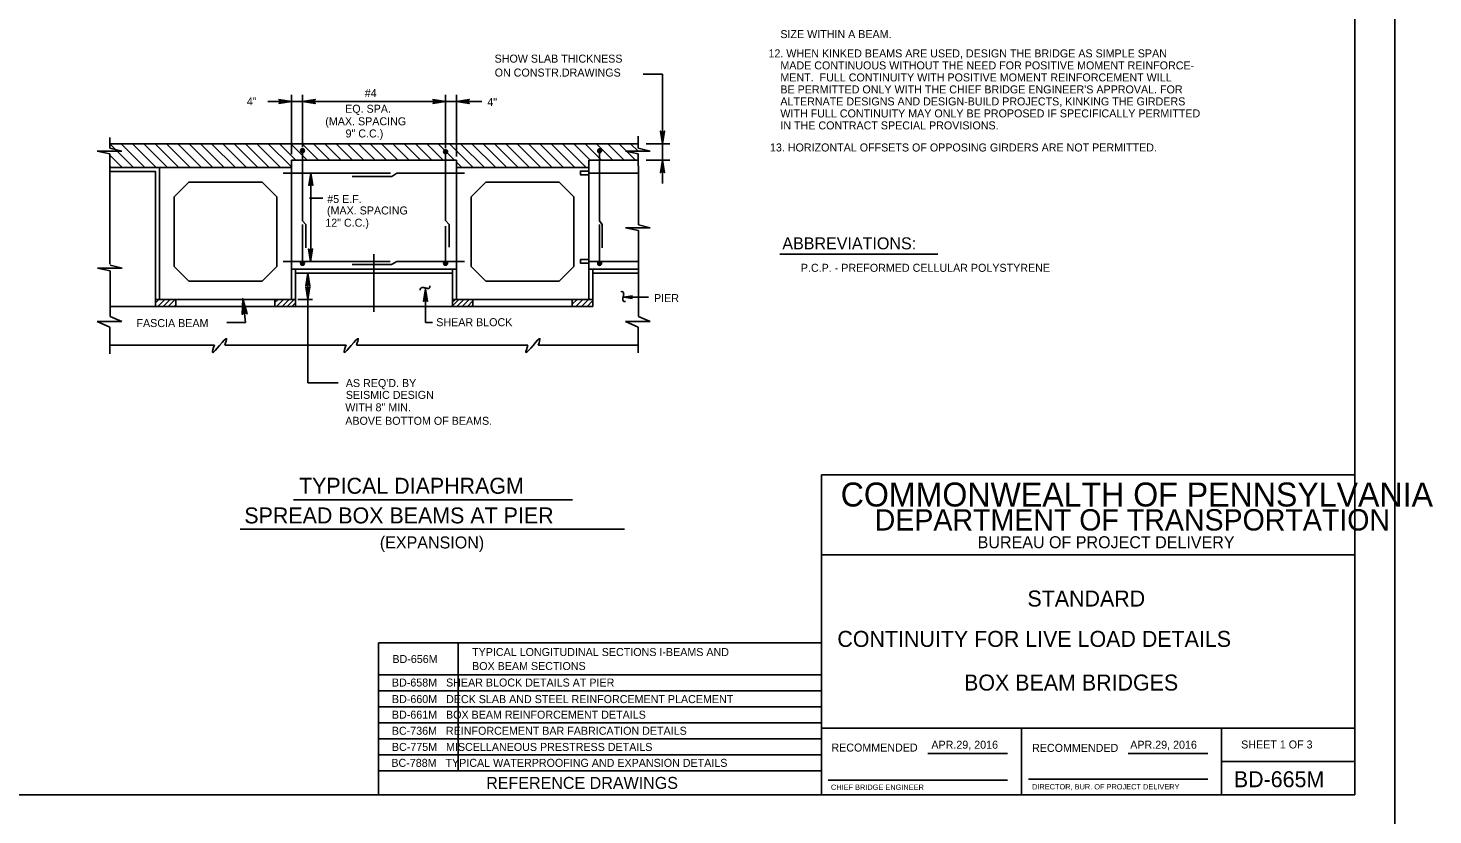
# Model space of a CAD drawing. Extents: x 641517 to 642372, y 298537 to 300319.
# Drawn here: x 641846 to 642372, y 299732 to 300027 of the extents above; entities that cross this region are included whole.
import ezdxf

# ---------------------------------------------------------------- set-up
doc = ezdxf.new("R2010")
doc.units = 0
doc.layers.add('2', color=7, linetype='Continuous')
doc.layers.add('PLT-BNDY', color=7, linetype='Continuous')

msp = doc.modelspace()

# ---------------------------------------------------------------- linework, layer by layer
at = {"layer": '2'}
for p, q in [((642343.05, 300303.62), (642343.05, 299739.62)), ((642076.21, 300009.91), (642083.47, 300009.91)), ((642083.47, 299983.78), (642083.47, 300009.91)), ((641948.58, 299999.66), (641935.58, 299999.66)), ((641944.45, 299979.91), (641944.45, 300002.14)), ((641948.58, 299982.53), (641948.58, 300002.14)), ((642002.2, 299999.66), (641948.58, 299999.66)), ((642002.2, 299982.16), (642002.2, 300002.14)), ((642015.83, 299999.66), (642002.2, 299999.66)), ((642006.33, 299979.03), (642006.33, 300002.14)), ((641876.33, 299982.16), (641876.33, 299986.16)), ((641876.33, 299983.78), (642074.33, 299983.78)), ((641876.33, 299983.78), (641876.33, 299983.78)), ((641876.33, 299983.78), (641885.2, 299974.91)), ((641880.57, 299983.78), (641889.45, 299974.91)), ((641884.81, 299983.78), (641893.69, 299974.91)), ((641889.06, 299983.78), (641897.93, 299974.91)), ((641893.3, 299983.78), (641902.17, 299974.91)), ((641897.54, 299983.78), (641906.42, 299974.91)), ((641901.79, 299983.78), (641910.66, 299974.91)), ((641906.03, 299983.78), (641914.9, 299974.91)), ((641910.27, 299983.78), (641919.15, 299974.91)), ((641914.51, 299983.78), (641923.39, 299974.91)), ((641918.76, 299983.78), (641927.63, 299974.91)), ((641923, 299983.78), (641931.87, 299974.91)), ((641927.24, 299983.78), (641936.12, 299974.91)), ((641931.48, 299983.78), (641940.36, 299974.91)), ((641935.73, 299983.78), (641944.45, 299975.05)), ((641939.97, 299983.78), (641946.09, 299977.66)), ((641944.21, 299983.78), (641950.34, 299977.66)), ((641948.45, 299983.78), (641954.58, 299977.66)), ((641952.7, 299983.78), (641958.82, 299977.66)), ((641956.94, 299983.78), (641963.06, 299977.66)), ((641961.18, 299983.78), (641967.31, 299977.66)), ((641965.42, 299983.78), (641971.55, 299977.66)), ((641969.67, 299983.78), (641975.79, 299977.66)), ((641973.91, 299983.78), (641980.04, 299977.66)), ((641978.15, 299983.78), (641984.28, 299977.66)), ((641982.4, 299983.78), (641988.52, 299977.66)), ((641986.64, 299983.78), (641992.76, 299977.66)), ((641990.88, 299983.78), (641997.01, 299977.66)), ((641995.12, 299983.78), (642001.25, 299977.66)), ((641999.37, 299983.78), (642005.49, 299977.66)), ((642003.61, 299983.78), (642012.48, 299974.91)), ((642007.85, 299983.78), (642016.73, 299974.91)), ((642012.09, 299983.78), (642020.97, 299974.91)), ((642016.34, 299983.78), (642025.21, 299974.91)), ((642020.58, 299983.78), (642029.45, 299974.91)), ((642024.82, 299983.78), (642033.7, 299974.91)), ((642029.06, 299983.78), (642037.94, 299974.91)), ((642033.31, 299983.78), (642042.18, 299974.91)), ((642037.55, 299983.78), (642046.42, 299974.91)), ((642041.79, 299983.78), (642050.67, 299974.91)), ((642046.03, 299983.78), (642054.91, 299974.91)), ((642050.28, 299983.78), (642056.4, 299977.66)), ((642054.52, 299983.78), (642060.65, 299977.66)), ((642058.76, 299983.78), (642064.89, 299977.66)), ((642063.01, 299983.78), (642069.13, 299977.66)), ((642067.25, 299983.78), (642073.37, 299977.66)), ((642071.49, 299983.78), (642074.33, 299980.94)), ((642074.33, 299982.16), (642074.33, 299986.66)), ((642086.27, 299983.78), (642077.34, 299983.78)), ((642083.47, 299977.66), (642083.47, 299983.78)), ((641880.83, 299981.03), (641871.58, 299981.03)), ((641876.33, 299980.03), (641871.58, 299981.03)), ((641880.83, 299981.03), (641876.33, 299982.16)), ((641876.33, 299938.63), (641876.33, 299980.03)), ((641876.33, 299979.54), (641880.96, 299974.91)), ((641948.58, 299981.16), (641948.58, 299954.91)), ((642002.2, 299955.03), (642002.2, 299980.78)), ((642059.95, 299981.16), (642059.95, 299954.91)), ((642078.83, 299981.03), (642069.58, 299981.03)), ((642074.33, 299980.03), (642069.58, 299981.03)), ((642078.83, 299981.03), (642074.33, 299982.16)), ((642074.33, 299975.53), (642074.33, 299980.03)), ((641876.33, 299975.3), (641876.72, 299974.91)), ((641944.45, 299974.91), (641876.33, 299974.91)), ((641893.45, 299973.41), (641876.33, 299973.41)), ((641893.45, 299922.79), (641893.45, 299973.41)), ((641894.95, 299925.41), (641894.95, 299974.91)), ((641894.95, 299974.91), (641894.95, 299974.91)), ((641944.45, 299977.66), (641944.45, 299925.41)), ((642006.33, 299977.66), (641944.45, 299977.66)), ((641944.45, 299977.66), (641944.45, 299974.91)), ((642006.33, 299974.91), (642006.33, 299977.66)), ((642006.33, 299976.82), (642008.24, 299974.91)), ((642055.83, 299974.91), (642006.33, 299974.91)), ((642006.33, 299974.91), (642006.33, 299925.41)), ((642055.83, 299974.91), (642006.33, 299974.91)), ((642074.33, 299977.66), (642055.83, 299977.66)), ((642055.83, 299977.66), (642055.83, 299974.91)), ((642055.83, 299977.66), (642055.83, 299926.41)), ((642074.45, 299977.66), (642055.83, 299977.66)), ((642055.83, 299977.66), (642055.83, 299974.91)), ((642055.83, 299974.91), (642055.83, 299925.41)), ((642074.45, 299953.41), (642074.45, 299975.53)), ((642086.27, 299977.66), (642077.34, 299977.66)), ((642083.47, 299968.91), (642083.47, 299977.66)), ((641900.45, 299963.91), (641905.95, 299969.41)), ((641905.95, 299969.41), (641933.45, 299969.41)), ((641933.45, 299969.41), (641938.95, 299963.91)), ((641981.5, 299972.78), (641941.35, 299972.78)), ((641951.67, 299939.65), (641951.67, 299972.78)), ((641982.08, 299971.47), (641967.2, 299971.47)), ((641983.95, 299972.78), (641982.08, 299971.47)), ((642009.25, 299972.78), (641983.95, 299972.78)), ((642011.83, 299963.91), (642017.33, 299969.41)), ((642017.33, 299969.41), (642044.83, 299969.41)), ((642044.83, 299969.41), (642050.33, 299963.91)), ((642074.45, 299972.78), (642055.58, 299972.78)), ((641900.45, 299937.78), (641900.45, 299963.91)), ((641938.95, 299963.91), (641938.95, 299937.78)), ((641956.18, 299963.35), (641951.67, 299963.35)), ((641953.46, 299963.35), (641951.67, 299963.35)), ((641953.46, 299963.35), (641951.67, 299963.35)), ((641953.46, 299963.35), (641951.67, 299963.35)), ((642011.83, 299937.78), (642011.83, 299963.91)), ((642050.33, 299963.91), (642050.33, 299937.78)), ((641948.58, 299954.91), (641949.8, 299953.49)), ((641948.58, 299953.52), (641948.58, 299938.91)), ((641949.8, 299953.49), (641949.8, 299944.78)), ((642002.2, 299955.03), (642003.51, 299953.54)), ((642002.2, 299938.91), (642002.2, 299952.86)), ((642003.51, 299945.03), (642003.51, 299953.54)), ((642059.95, 299954.91), (642060.95, 299953.51)), ((642059.95, 299953.49), (642059.95, 299938.91)), ((642060.95, 299953.51), (642060.95, 299944.78)), ((642078.83, 299952.28), (642069.58, 299952.28)), ((642074.45, 299951.28), (642069.58, 299952.28)), ((642078.83, 299952.28), (642074.45, 299953.41)), ((642074.45, 299942.66), (642074.45, 299951.28)), ((641975.33, 299942.41), (641975.33, 299920.78)), ((642074.45, 299919.03), (642074.45, 299942.66)), ((642127.54, 299942.42), (642186.76, 299942.42)), ((641880.95, 299937.12), (641871.7, 299937.12)), ((641876.45, 299936.12), (641871.7, 299937.12)), ((641880.95, 299937.12), (641876.45, 299938.24)), ((641900.45, 299937.78), (641905.95, 299932.28)), ((641938.95, 299937.78), (641933.45, 299932.28)), ((641981.39, 299939.66), (641941.35, 299939.66)), ((642006.33, 299936.78), (641944.45, 299936.78)), ((641945.95, 299936.78), (641945.95, 299922.79)), ((641981.91, 299938.43), (641967.2, 299938.43)), ((641983.95, 299939.66), (641981.91, 299938.43)), ((642009.25, 299939.66), (641983.95, 299939.66)), ((642004.83, 299936.78), (642004.83, 299922.79)), ((642011.83, 299937.78), (642017.33, 299932.28)), ((642050.33, 299937.78), (642044.83, 299932.28)), ((642074.45, 299939.66), (642055.7, 299939.66)), ((642074.45, 299936.78), (642055.83, 299936.78)), ((642055.83, 299936.67), (642055.94, 299936.78)), ((642057.33, 299936.78), (642057.33, 299922.79)), ((641876.45, 299919.03), (641876.45, 299936.12)), ((641933.45, 299932.28), (641905.95, 299932.28)), ((642004.83, 299935.28), (641945.95, 299935.28)), ((641950.58, 299925.41), (641950.58, 299935.28)), ((642044.83, 299932.28), (642017.33, 299932.28)), ((642074.45, 299935.28), (642057.33, 299935.28)), ((641994.7, 299916.73), (641994.7, 299929.41)), ((642078.2, 299926.28), (642068.95, 299926.28)), ((641945.95, 299922.79), (641876.45, 299922.79)), ((641945.95, 299925.41), (641893.45, 299925.41)), ((641894.76, 299925.39), (641893.46, 299924.09)), ((641896.94, 299925.39), (641894.33, 299922.78)), ((641898.96, 299925.39), (641896.35, 299922.78)), ((641900.88, 299925.39), (641898.27, 299922.79)), ((641901.07, 299923.37), (641900.48, 299922.78)), ((641901.08, 299922.79), (641901.08, 299925.41)), ((641901.08, 299925.41), (641938.2, 299925.41)), ((641926.19, 299925.64), (641927.25, 299916.8)), ((641938.2, 299922.79), (641938.2, 299925.41)), ((641939.39, 299925.39), (641938.21, 299924.22)), ((641941.46, 299925.4), (641938.85, 299922.79)), ((641943.55, 299925.39), (641940.95, 299922.79)), ((641945.43, 299925.39), (641942.83, 299922.79)), ((641945.94, 299924.18), (641944.57, 299922.8)), ((642004.83, 299922.79), (641945.95, 299922.79)), ((641952.26, 299925.41), (641946.86, 299925.41)), ((641950.58, 299894.18), (641950.58, 299925.41)), ((642057.33, 299925.41), (642004.83, 299925.41)), ((642057.33, 299922.79), (642004.83, 299922.79)), ((642004.84, 299924.49), (642005.75, 299925.4)), ((642004.84, 299923.03), (642007.19, 299925.38)), ((642006.41, 299922.79), (642009.02, 299925.4)), ((642008.4, 299922.8), (642011.01, 299925.41)), ((642010.38, 299922.79), (642012.46, 299924.87)), ((642012.05, 299922.8), (642012.45, 299923.21)), ((642012.45, 299922.79), (642012.45, 299925.41)), ((642012.45, 299925.41), (642049.58, 299925.41)), ((642049.7, 299922.79), (642049.7, 299925.41)), ((642051.51, 299925.4), (642049.7, 299923.59)), ((642053.65, 299925.4), (642051.05, 299922.79)), ((642055.76, 299925.4), (642053.15, 299922.79)), ((642055.25, 299922.79), (642057.31, 299924.85)), ((641880.83, 299917.16), (641871.58, 299917.16)), ((641876.33, 299915.03), (641871.58, 299917.16)), ((641880.83, 299917.16), (641876.45, 299919.03)), ((641927.25, 299916.8), (641920.19, 299916.8)), ((641997.32, 299916.73), (641994.7, 299916.73)), ((642078.83, 299917.16), (642069.58, 299917.16)), ((642074.33, 299915.03), (642069.58, 299917.16)), ((642078.83, 299917.16), (642074.45, 299919.03)), ((641876.33, 299905.03), (641876.33, 299915.03)), ((642074.33, 299905.41), (642074.33, 299915.03)), ((641915.58, 299908.28), (641876.33, 299908.28)), ((641964.95, 299908.28), (641919.45, 299908.28)), ((642033.08, 299908.28), (641968.83, 299908.28)), ((642074.33, 299908.28), (642036.95, 299908.28)), ((641961.96, 299894.18), (641950.58, 299894.18)), ((642343.05, 299859.62), (642143.05, 299859.62)), ((642143.05, 299859.62), (642143.05, 299739.62)), ((642343.05, 299739.62), (642343.05, 299859.62)), ((641945.13, 299850.28), (642049.76, 299850.28)), ((641925.26, 299839.28), (642069.26, 299839.28)), ((642343.05, 299829.62), (642143.05, 299829.62)), ((641977.08, 299796.62), (642143.05, 299796.62)), ((641977.08, 299796.62), (641977.08, 299739.62)), ((642006.95, 299748.62), (642006.95, 299796.62)), ((641977.08, 299784.62), (642143.05, 299784.62)), ((641977.08, 299778.62), (642143.05, 299778.62)), ((641977.08, 299772.62), (642143.05, 299772.62)), ((641977.08, 299766.62), (642143.05, 299766.62)), ((642343.05, 299764.62), (642143.05, 299764.62)), ((642218.05, 299739.62), (642218.05, 299764.62)), ((642293.05, 299764.62), (642293.05, 299739.62)), ((641977.08, 299760.62), (642143.05, 299760.62)), ((641977.08, 299754.62), (642143.05, 299754.62)), ((642183.01, 299755.12), (642212.78, 299755.12)), ((642258.01, 299755.12), (642287.92, 299755.12)), ((642293.05, 299752.12), (642343.05, 299752.12)), ((641977.08, 299748.62), (642143.05, 299748.62)), ((642145.55, 299745.12), (642212.78, 299745.12)), ((642220.67, 299745.5), (642287.92, 299745.5)), ((642343.05, 299739.62), (641557.05, 299739.62)), ((642143.05, 299739.62), (642343.05, 299739.62))]:
    msp.add_line(p, q, dxfattribs=at)
for points in [[(641939.95, 300000.16), (641940.08, 299999.91), (641944.45, 299999.66), (641939.95, 300000.16), (641939.7, 300000.41), (641944.45, 299999.66), (641940.08, 299999.41), (641939.95, 299999.16), (641944.45, 299999.66), (641939.7, 299998.91), (641939.95, 299999.16)], [(641953.08, 299999.03), (641952.95, 299999.41), (641948.58, 299999.66), (641953.08, 299999.03), (641953.33, 299998.91), (641948.58, 299999.66), (641952.95, 299999.91), (641953.08, 300000.16), (641948.58, 299999.66), (641953.33, 300000.41), (641953.08, 300000.16)], [(641997.7, 300000.16), (641997.83, 299999.91), (642002.2, 299999.66), (641997.7, 300000.16), (641997.45, 300000.41), (642002.2, 299999.66), (641997.83, 299999.41), (641997.7, 299999.16), (642002.2, 299999.66), (641997.45, 299998.91), (641997.7, 299999.16)], [(642010.83, 299999.03), (642010.7, 299999.41), (642006.33, 299999.66), (642010.83, 299999.03), (642011.08, 299998.91), (642006.33, 299999.66), (642010.7, 299999.91), (642010.83, 300000.16), (642006.33, 299999.66), (642011.08, 300000.41), (642010.83, 300000.16)], [(641876.33, 299983.78), (641876.45, 299983.78)], [(642084.09, 299988.28), (642083.72, 299988.16), (642083.47, 299983.78), (642084.09, 299988.28), (642084.22, 299988.53), (642083.47, 299983.78), (642083.22, 299988.16), (642082.97, 299988.28), (642083.47, 299983.78), (642082.72, 299988.53), (642082.97, 299988.28)], [(642074.33, 299977.66), (642074.33, 299977.66)], [(642082.97, 299973.16), (642083.22, 299973.41), (642083.47, 299977.66), (642082.97, 299973.16), (642082.72, 299972.91), (642083.47, 299977.66), (642083.72, 299973.41), (642083.97, 299973.16), (642083.47, 299977.66), (642084.22, 299972.91), (642083.97, 299973.16)], [(641951.04, 299968.28), (641951.42, 299968.53), (641951.67, 299972.78), (641951.04, 299968.28), (641950.92, 299968.16), (641951.67, 299972.78), (641951.79, 299968.53), (641952.17, 299968.41), (641951.67, 299972.78), (641952.42, 299968.16), (641952.17, 299968.41)], [(641952.08, 299944.11), (641951.83, 299943.99), (641951.58, 299939.61), (641952.08, 299944.11), (641952.33, 299944.36), (641951.58, 299939.61), (641951.33, 299943.99), (641950.95, 299944.11), (641951.58, 299939.61), (641950.83, 299944.36), (641950.95, 299944.11)], [(641950.08, 299930.78), (641950.33, 299930.91), (641950.58, 299935.28), (641950.08, 299930.78), (641949.83, 299930.53), (641950.58, 299935.28), (641950.83, 299930.91), (641951.2, 299930.78), (641950.58, 299935.28), (641951.33, 299930.53), (641951.2, 299930.78)], [(641951.2, 299929.91), (641950.83, 299929.66), (641950.58, 299925.41), (641951.2, 299929.91), (641951.33, 299930.16), (641950.58, 299925.41), (641950.45, 299929.66), (641950.08, 299929.91), (641950.58, 299925.41), (641949.83, 299930.16), (641950.08, 299929.91)], [(641994.2, 299924.91), (641994.45, 299925.03), (641994.7, 299929.41), (641994.2, 299924.91), (641993.95, 299924.66), (641994.7, 299929.41), (641994.95, 299925.03), (641995.33, 299924.91), (641994.7, 299929.41), (641995.45, 299924.66), (641995.33, 299924.91)], [(642071.95, 299925.91), (642071.83, 299926.16), (642068.95, 299926.28), (642071.95, 299925.91), (642072.08, 299925.78), (642068.95, 299926.28), (642071.83, 299926.41), (642071.95, 299926.66), (642068.95, 299926.28), (642072.08, 299926.78), (642071.95, 299926.66)], [(641926.16, 299920.06), (641926.54, 299920.32), (641926.19, 299925.64), (641926.16, 299920.06), (641925.95, 299919.75), (641926.19, 299925.64), (641927.09, 299920.39), (641927.51, 299920.24), (641926.19, 299925.64), (641927.8, 299919.97), (641927.51, 299920.24)]]:
    msp.add_lwpolyline(points, dxfattribs=at)
for points in [[(641876.33, 299974.91), (641876.33, 299973.41), (641893.45, 299973.41), (641893.45, 299925.41), (641894.95, 299925.41), (641894.95, 299974.91)], [(642055.83, 299973.5), (642052.72, 299973.5), (642052.72, 299972.14), (642055.83, 299972.14)], [(641944.45, 299936.78), (641944.45, 299925.41), (641945.95, 299925.41), (641945.95, 299936.78)], [(641945.95, 299936.78), (641945.95, 299935.28), (642004.83, 299935.28), (642004.83, 299936.78)], [(642004.83, 299936.78), (642004.83, 299925.41), (642006.33, 299925.41), (642006.33, 299936.78)], [(642055.83, 299940.36), (642052.72, 299940.36), (642052.72, 299939.01), (642055.83, 299939.01)], [(642055.83, 299925.41), (642057.33, 299925.41), (642057.33, 299936.78), (642055.83, 299936.78)], [(642057.33, 299936.78), (642057.33, 299935.28), (642074.45, 299935.28), (642074.45, 299936.78)]]:
    msp.add_lwpolyline(points, close=True, dxfattribs=at)
for centre, radius in [((641948.58, 299981.16), 0.723), ((641948.58, 299981.16), 0.516), ((641948.58, 299981.16), 0.282), ((641948.58, 299981.16), 0.142), ((641948.58, 299981.16), 0.061), ((642002.2, 299980.78), 0.723), ((642002.2, 299980.78), 0.516), ((642002.2, 299980.78), 0.282), ((642002.2, 299980.78), 0.142), ((642002.2, 299980.78), 0.061), ((642059.93, 299981.14), 0.723), ((642059.93, 299981.14), 0.516), ((642059.93, 299981.14), 0.282), ((642059.95, 299981.21), 0.257), ((642059.93, 299981.14), 0.142), ((642059.93, 299981.14), 0.061), ((641951.67, 299963.35), 0.276), ((641951.67, 299963.35), 0.276), ((641951.67, 299963.35), 0.276), ((641951.67, 299963.35), 0.276), ((641948.58, 299938.91), 0.723), ((641948.58, 299938.91), 0.516), ((641948.58, 299938.91), 0.282), ((641948.58, 299938.91), 0.142), ((641948.58, 299938.91), 0.061), ((642002.2, 299938.91), 0.723), ((642002.2, 299938.91), 0.516), ((642002.2, 299938.91), 0.282), ((642002.2, 299938.91), 0.142), ((642002.2, 299938.91), 0.061), ((642059.94, 299938.9), 0.723), ((642059.94, 299938.9), 0.516), ((642059.94, 299938.9), 0.282), ((642059.94, 299938.9), 0.142), ((642059.94, 299938.9), 0.061)]:
    msp.add_circle(centre, radius, dxfattribs=at)
for points in [[(641992.7, 299928.91), (641992.83, 299929.53), (641993.08, 299929.78), (641993.7, 299929.91), (641994.33, 299929.78), (641994.83, 299929.66), (641995.45, 299929.53), (641996.08, 299929.66), (641996.33, 299930.03), (641996.33, 299930.53)], [(642067.83, 299928.28), (642068.58, 299928.28), (642068.83, 299927.91), (642068.95, 299927.28), (642068.83, 299926.78), (642068.7, 299926.16), (642068.58, 299925.53), (642068.7, 299924.91), (642069.08, 299924.66), (642069.58, 299924.66)], [(641915.58, 299908.28), (641914.83, 299905.53), (641920.08, 299910.66), (641919.45, 299908.28)], [(641964.95, 299908.28), (641964.2, 299905.53), (641969.45, 299910.66), (641968.83, 299908.28)], [(642033.08, 299908.28), (642032.33, 299905.53), (642037.58, 299910.66), (642036.95, 299908.28)]]:
    msp.add_spline(points, degree=3, dxfattribs=at)
at = {"layer": 'PLT-BNDY'}
msp.add_lwpolyline([(641517.05, 300318.62), (642358.05, 300318.62), (642358.05, 299724.62), (641517.05, 299724.62)], close=True, dxfattribs=at)

# ---------------------------------------------------------------- texts
at = {"layer": '2'}
for s, height, p in [('    SIZE WITHIN A BEAM.', 3, (642123.23, 300023.38)), ('SHOW SLAB THICKNESS', 3, (642020.57, 300014.18)), ('12. WHEN KINKED BEAMS ARE USED, DESIGN THE BRIDGE AS SIMPLE SPAN', 3, (642123.23, 300016.14)), ('ON CONSTR.DRAWINGS', 3, (642020.6, 300008.95)), ('    MADE CONTINUOUS WITHOUT THE NEED FOR POSITIVE MOMENT REINFORCE-', 3, (642123.23, 300011.64)), ('    MENT.  FULL CONTINUITY WITH POSITIVE MOMENT REINFORCEMENT WILL', 3, (642123.23, 300007.14)), ("    BE PERMITTED ONLY WITH THE CHIEF BRIDGE ENGINEER'S APPROVAL. FOR", 3, (642123.23, 300002.64)), ('4"', 3, (641927.71, 299998.16)), ('#4', 3, (641971.91, 300001.26)), ('4"', 3, (642017.84, 299997.91)), ('    ALTERNATE DESIGNS AND DESIGN-BUILD PROJECTS, KINKING THE GIRDERS ', 3, (642123.23, 299998.14)), ('EQ. SPA.', 3, (641964.55, 299995.39)), ('    WITH FULL CONTINUITY MAY ONLY BE PROPOSED IF SPECIFICALLY PERMITTED', 3, (642123.23, 299993.64)), ('(MAX. SPACING', 3, (641957.11, 299990.68)), ('9" C.C.)', 3, (641964.71, 299986.12)), ('    IN THE CONTRACT SPECIAL PROVISIONS.', 3, (642123.23, 299989.14)), ('13. HORIZONTAL OFFSETS OF OPPOSING GIRDERS ARE NOT PERMITTED.', 2.9987, (642123.79, 299980.87)), ('#5 E.F.', 3, (641957.83, 299961.53)), ('(MAX. SPACING', 3, (641957.74, 299957.25)), ('12" C.C.)', 3, (641957.1, 299952.66)), ('ABBREVIATIONS:', 4.5, (642128.43, 299944.17)), ('P.C.P. - PREFORMED CELLULAR POLYSTYRENE', 3, (642135.36, 299935.75)), ('PIER', 3, (642080.33, 299924.41)), ('FASCIA BEAM', 3, (641886.34, 299915.03)), ('SHEAR BLOCK', 3, (641998.69, 299915.36)), ("AS REQ'D. BY", 3, (641964.8, 299892.54)), ('SEISMIC DESIGN', 3, (641964.8, 299888.1)), ('WITH 8" MIN.', 3, (641964.59, 299883.45)), ('ABOVE BOTTOM OF BEAMS.', 3, (641964.59, 299878.39)), ('TYPICAL DIAPHRAGM', 6, (641947.26, 299852.53)), ('COMMONWEALTH OF PENNSYLVANIA', 9, (642150.3, 299847.75)), ('SPREAD BOX BEAMS AT PIER', 6, (641926.76, 299841.41)), ('DEPARTMENT OF TRANSPORTATION', 8.0002, (642163.05, 299838.75)), ('(EXPANSION)', 4.5, (641977.54, 299832.03)), ('BUREAU OF PROJECT DELIVERY', 4.5, (642201.64, 299832.12)), ('STANDARD', 6, (642220.3, 299810.25)), ('CONTINUITY FOR LIVE LOAD DETAILS', 6, (642149.05, 299795.12)), ('TYPICAL LONGITUDINAL SECTIONS I-BEAMS AND ', 3, (642012.13, 299791.69)), ('BD-656M', 3, (641982.26, 299789.07)), ('BOX BEAM SECTIONS', 3, (642012.13, 299786.44)), ('BOX BEAM BRIDGES', 6, (642196.55, 299778.75)), ('BD-658M   SHEAR BLOCK DETAILS AT PIER', 3, (641982.08, 299780.25)), ('BD-660M   DECK SLAB AND STEEL REINFORCEMENT PLACEMENT', 3, (641982.09, 299774.04)), ('BD-661M   BOX BEAM REINFORCEMENT DETAILS', 3, (641982.07, 299768.2)), ('BC-736M   REINFORCEMENT BAR FABRICATION DETAILS', 3, (641982.04, 299762.17)), ('BC-775M   MISCELLANEOUS PRESTRESS DETAILS', 3, (641982.08, 299756.11)), ('RECOMMENDED', 3, (642146.82, 299755.87)), ('APR.29, 2016', 3, (642184.29, 299756.94)), ('APR.29, 2016', 3, (642258.83, 299756.94)), ('SHEET 1 OF 3', 3, (642300.41, 299757.04)), ('BC-788M   TYPICAL WATERPROOFING AND EXPANSION DETAILS', 3, (641981.88, 299750.14)), ('BD-665M', 6, (642297.67, 299742.5)), ('REFERENCE DRAWINGS', 4.5, (642017.42, 299741.87)), ('CHIEF BRIDGE ENGINEER', 2.0002, (642146.64, 299741.5)), ('DIRECTOR, BUR. OF PROJECT DELIVERY', 2.0002, (642222.03, 299741.68))]:
    msp.add_text(s, height=height, dxfattribs=at).set_placement(p)
msp.add_text('RECOMMENDED', height=3, rotation=360, dxfattribs=at).set_placement((642222.03, 299755.75))

doc.saveas('drawing.dxf')
